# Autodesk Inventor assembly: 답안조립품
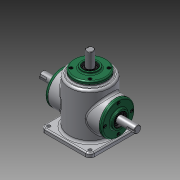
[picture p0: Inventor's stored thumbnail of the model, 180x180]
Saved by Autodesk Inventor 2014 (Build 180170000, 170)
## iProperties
Created: 2015-10
Part Number: 답안조립품
Document SubType Name: Assembly
Designer: Administrator
Author: Administrator
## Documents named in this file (14)
- C:\Users\Administrator\Desktop\451007V1018\답안조립품.iam
- C:\Users\Administrator\Desktop\451007V1018\1-본체.ipt
- C:\Users\Administrator\Desktop\451007V1018\메인 베벨기어.ipt
- C:\Users\Administrator\Desktop\451007V1018\메인 축.ipt
- 메인 축.ipt
- C:\Users\Administrator\Desktop\451007V1018\키 5x5.ipt
- C:\Users\Administrator\Desktop\451007V1018\베어링 6203.ipt
- C:\Users\Administrator\Desktop\451007V1018\커버.ipt
- C:\Users\Administrator\Desktop\451007V1018\M4.ipt
- C:\Users\Administrator\Desktop\451007V1018\오일실.ipt
- C:\Users\Administrator\Desktop\451007V1018\서브 축.ipt
- 서브 축.ipt
- C:\Users\Administrator\Desktop\451007V1018\서브 베벨기어.ipt
- C:\Users\Administrator\Desktop\451007V1018\키 4x4.ipt
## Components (13 placed, 2 different names)
1. 1-본체:2
2. M4:1
3. M4:2
4. M4:3
5. M4:4
6. M4:5
7. M4:6
8. M4:7
9. M4:8
10. M4:9
11. M4:10
12. M4:11
13. M4:12
## Named parameters: d6_d5 = 0, d7_d0 = 0, d8_d1 = 0, d9_d2 = 0, d10_d3 = 0, d11_d4 = 0, d16_d6_d5 = 0, d17_d7_d0 = 0, d18_d8_d1 = 0, d19_d9_d2 = 0, d20_d10_d3 = 0, d21_d11_d4 = 0, d22_d12 = 0, d23_d13 = 0, d24_d14 = 0, d25_d15 = 0
